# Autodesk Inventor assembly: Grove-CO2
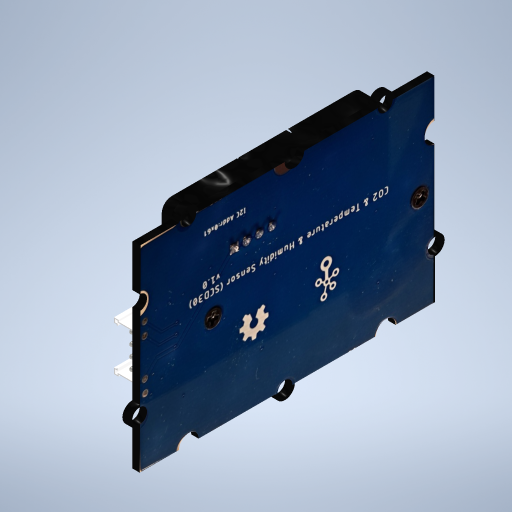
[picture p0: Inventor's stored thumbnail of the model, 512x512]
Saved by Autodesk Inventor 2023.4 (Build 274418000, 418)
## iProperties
Created: 2025-02
Part Number: Grove-CO2
Document SubType Name: Assembly
Designer: bruno
Author: bruno
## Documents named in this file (4)
- C:\Users\bruno\Documents\1-Cours-2024-25\1STI2D\IT\Escape-game\Inventor_uhl\Boite\Grove-CO2\Grove-CO2.iam
- C:\Users\bruno\Documents\1-Cours-2024-25\1STI2D\IT\Escape-game\Inventor_uhl\Boite\Grove-CO2\CO2-Sensor.ipt
- C:\Users\bruno\Documents\1-Cours-2024-25\1STI2D\IT\Escape-game\Inventor_uhl\Boite\Grove-CO2\boitier.ipt
- C:\Users\bruno\Documents\1-Cours-2024-25\1STI2D\IT\Escape-game\Inventor_uhl\Boite\Grove-CO2\connecteur.ipt
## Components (3 placed, 3 different names)
1. CO2-Sensor:1 — Placage:1, Placage:2, Affleurement:1, Affleurement:2, Tangente:1, Affleurement:3
2. boitier:1 — Placage:1, Affleurement:2, Tangente:1
3. connecteur:1 — Placage:2, Affleurement:1, Affleurement:3
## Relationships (6: Flush 3, Mate 2, Tangent 1)
- Placage:1 [Mate]: CO2-Sensor:1 ↔ boitier:1
- Placage:2 [Mate]: CO2-Sensor:1 ↔ connecteur:1
- Affleurement:1 [Flush]: CO2-Sensor:1 ↔ connecteur:1
- Affleurement:2 [Flush]: CO2-Sensor:1 ↔ boitier:1
- Tangente:1: CO2-Sensor:1 ↔ boitier:1
- Affleurement:3 [Flush]: CO2-Sensor:1 ↔ connecteur:1
